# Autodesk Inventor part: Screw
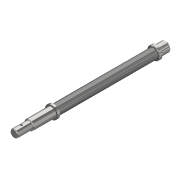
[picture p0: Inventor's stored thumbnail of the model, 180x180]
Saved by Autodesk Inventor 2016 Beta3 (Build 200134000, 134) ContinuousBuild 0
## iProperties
Created: 2016-02
Part Number: Screw
Material: Steel, High Strength, Low Alloy
Document SubType Name: Modeling
Designer: Vertex
Density: 7.85 g/cm^3
Appearance: Steel - Polished
Mass: 753.932 g
Surface Area: 206.303 cm^2
Volume: 96.0424 cm^3
Author: Vertex
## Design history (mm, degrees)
sketch "Sketch1"
  geometry: C1 r 10 at (0, 0); 1 further point
  constraints: 1 centre point, 1 coincident
  dimensions: "d0" = 20 diameter of C1
extrude "Extrusion1" new body sketch "Sketch1" distance "d1" = 20; taper "d2" = 0 deg
sketch "Sketch2"
  geometry: C1 r 13 at (0, 0); 1 further point
  constraints: 1 centre point, 1 coincident
  dimensions: "d3" = 26 diameter of C1
extrude "Extrusion2" join sketch "Sketch2" distance "d4" = 6; taper "d5" = 0 deg
sketch "Sketch3"
  geometry: C1 r 10 at (0, 0); 1 further point
  constraints: 1 centre point, 1 coincident
  dimensions: "d6" = 20 diameter of C1
extrude "Extrusion3" join sketch "Sketch3" distance "d7" = 201.4; taper "d8" = 0 deg
sketch "Sketch4"
  geometry: C1 r 13 at (0, 0); 1 further point
  constraints: 1 centre point, 1 coincident
  dimensions: "d9" = 26 diameter of C1
extrude "Extrusion4" join sketch "Sketch4" distance "d10" = 6; taper "d11" = 0 deg
sketch "Sketch5"
  geometry: C1 r 10 at (0, 0); 1 further point
  constraints: 1 centre point, 1 coincident
  dimensions: "d12" = 20 diameter of C1
extrude "Extrusion5" join sketch "Sketch5" distance "d13" = 46; taper "d14" = 0 deg
sketch "Sketch6"
  geometry: C1 r 8 at (0, 0); 1 further point
  constraints: 1 centre point, 1 coincident
  dimensions: "d15" = 16 diameter of C1
extrude "Extrusion6" join sketch "Sketch6" distance "d16" = 30; taper "d17" = 0 deg
workplane "Work Plane1"
sketch "Sketch7"
  geometry: L1 (10, 279.4)-(-10, 279.4) reference; L2 (8, 309.4)-(-8, 309.4) reference; C1 r 2.5 at (0, 294.4); 1 further point
  constraints: 1 centre point
  dimensions: "d20" = 15 distance from line of C1.centre L2; "d21" = 5 diameter of C1
chamfer "Chamfer1" distance "d22" = 1.25; stored, may be unused: second distance "d23" = 1.25, angle "d24" = 45 deg
hole "Hole1" sketch "Sketch7" diameter "d25" = 4.13; stored, may be unused: countersink angle "d29" = 90 deg, drill point angle "d31" = 118 deg; dims "d26" = 6, "d27" = 3.75, "d28" = 2.5, "d30" = 8
thread "Thread1" dims "d32" = 200, "d33" = 0
body "Solid1"
other parameters: "d18" = 8
